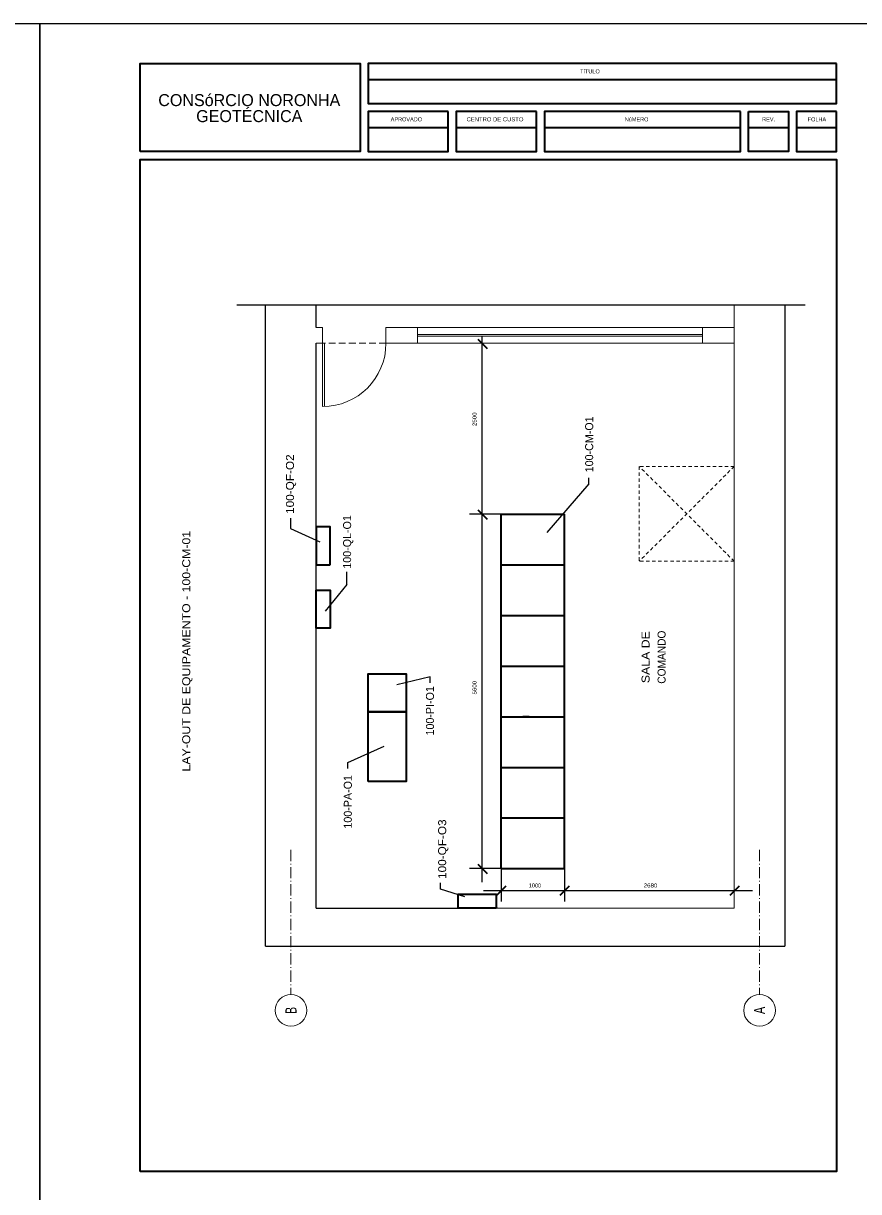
# Model space of a CAD drawing. Extents: x -4160 to -2690, y -474 to 714.
# Drawn here: x -3323.9 to -3115.3, y 422.5 to 714.5 of the extents above; entities that cross this region are included whole.
import ezdxf
from ezdxf.enums import TextEntityAlignment as Align

# ---------------------------------------------------------------- set-up
doc = ezdxf.new("R2010")
doc.units = 0
doc.header["$LTSCALE"] = 0.56
for name, pattern in [('DOT_DASHED', [7.7, 5, -1.2, 0.3, -1.2]), ('MEDIUM_DASHED', [4.5, 3, -1.5]), ('SHORT_DASHED', [2.7, 1.5, -1.2])]:
    doc.linetypes.add(name, pattern=pattern)
for name, color, linetype, lineweight in [('1', 7, 'Continuous', 25), ('2', 7, 'Continuous', 25), ('5', 7, 'Continuous', 35)]:
    doc.layers.add(name, color=color, linetype=linetype, lineweight=lineweight)

msp = doc.modelspace()

# ---------------------------------------------------------------- linework, layer by layer
at = {"layer": '1'}
for p, q in [((-3263.3911, 483.853), (-3263.3911, 644.139)), ((-3250.7364, 638.4791), (-3250.7364, 644.139)), ((-3133.6792, 644.139), (-3133.6792, 483.853)), ((-3250.7364, 493.344), (-3250.7364, 634.5246)), ((-3182.6851, 599.3822), (-3193.141, 587.226)), ((-3182.6851, 599.3822), (-3182.6851, 600.9021)), ((-3243.1054, 574.2496), (-3243.1054, 577.3547)), ((-3243.1054, 574.2496), (-3248.5217, 567.522)), ((-3188.7672, 565.6996), (-3188.7672, 554.6265)), ((-3197.5862, 541.1952), (-3199.1679, 541.1952)), ((-3197.5862, 541.1952), (-3189.3606, 541.1952)), ((-3188.7672, 541.9861), (-3188.7672, 527.7494)), ((-3242.8779, 529.7514), (-3233.7909, 533.8527)), ((-3242.8779, 528.2312), (-3242.8779, 529.7514)), ((-3219.7416, 498.1056), (-3219.7416, 499.6254)), ((-3213.6246, 496.1346), (-3219.7416, 498.1056)), ((-3250.7364, 493.344), (-3215.3027, 493.344)), ((-3205.5111, 493.344), (-3205.8117, 493.344)), ((-3263.3911, 483.853), (-3133.6792, 483.853))]:
    msp.add_line(p, q, dxfattribs=at)
at = {"layer": '1', "lineweight": 13}
for p, q in [((-3146.3342, 644.139), (-3146.3342, 493.344)), ((-3249.1546, 638.4791), (-3250.7364, 638.4791)), ((-3249.1546, 634.5246), (-3249.1546, 638.4791)), ((-3233.336, 638.4791), (-3225.4269, 638.4791)), ((-3233.336, 634.5246), (-3233.336, 638.4791)), ((-3225.4269, 638.4791), (-3154.2433, 638.4791)), ((-3154.2433, 636.739), (-3225.4269, 636.739)), ((-3164.5552, 638.4791), (-3158.7042, 638.4791)), ((-3154.2433, 638.4791), (-3146.3342, 638.4791)), ((-3154.2433, 634.5246), (-3154.2433, 638.4791)), ((-3249.1546, 634.5246), (-3250.7364, 634.5246)), ((-3249.1546, 634.5246), (-3249.1546, 618.706)), ((-3248.68, 634.5246), (-3249.1546, 634.5246)), ((-3248.68, 618.706), (-3248.68, 634.5246)), ((-3154.2433, 636.2645), (-3225.4269, 636.2645)), ((-3225.4269, 634.5246), (-3154.2433, 634.5246)), ((-3165.6768, 634.5246), (-3165.2024, 634.5246)), ((-3165.2024, 634.5246), (-3163.6204, 634.5246)), ((-3154.2433, 634.5246), (-3146.3342, 634.5246)), ((-3250.7364, 493.344), (-3146.3342, 493.344))]:
    msp.add_line(p, q, dxfattribs=at)
at = {"layer": '1', "linetype": 'MEDIUM_DASHED', "lineweight": 13}
msp.add_line((-3233.336, 634.5246), (-3248.68, 634.5246), dxfattribs=at)
at = {"layer": '1', "linetype": 'SHORT_DASHED', "lineweight": 13}
for p, q in [((-3146.3342, 603.7575), (-3170.0617, 580.0296)), ((-3146.3342, 580.0296), (-3170.0617, 603.7575)), ((-3146.3342, 603.7575), (-3170.0617, 603.7575)), ((-3170.0617, 603.7575), (-3170.0617, 580.0296)), ((-3146.3342, 580.0296), (-3170.0617, 580.0296))]:
    msp.add_line(p, q, dxfattribs=at)
at = {"layer": '1', "lineweight": 35}
for p, q in [((-3204.5794, 503.2164), (-3204.5794, 591.8002)), ((-3204.5794, 591.8002), (-3188.7609, 591.8002)), ((-3188.7609, 503.2164), (-3188.7609, 591.8002)), ((-3204.5794, 579.1454), (-3188.7609, 579.1454)), ((-3204.5794, 566.4907), (-3188.7609, 566.4907)), ((-3204.5794, 553.8356), (-3188.7609, 553.8356)), ((-3204.5794, 541.181), (-3188.7609, 541.181)), ((-3204.5794, 528.5261), (-3188.7609, 528.5261)), ((-3204.5794, 515.8713), (-3188.7609, 515.8713)), ((-3204.5794, 503.2164), (-3188.7609, 503.2164))]:
    msp.add_line(p, q, dxfattribs=at)
at = {"layer": '1', "linetype": 'DOT_DASHED', "lineweight": 13}
for p, q in [((-3257.064, 507.9161), (-3257.064, 471.7343)), ((-3140.0067, 507.9161), (-3140.0067, 471.7343))]:
    msp.add_line(p, q, dxfattribs=at)
at = {"layer": '1', "lineweight": 13}
msp.add_lwpolyline([(-3233.336, 634.5246), (-3225.4269, 634.5246), (-3225.4269, 638.4791)], dxfattribs=at)
at = {"layer": '1'}
for points in [[(-3257.2015, 590.8481), (-3257.2015, 588.252), (-3249.855, 584.9225)], [(-3222.2946, 549.6233), (-3222.2946, 551.1436), (-3230.5835, 549.1583)]]:
    msp.add_lwpolyline(points, dxfattribs=at)
msp.add_lwpolyline([(-3188.7609, 591.8002), (-3188.7609, 503.2164), (-3204.5794, 503.2164), (-3204.5794, 591.8002)], close=True, dxfattribs=at)
at = {"layer": '1', "lineweight": 35}
for points in [[(-3250.7364, 563.3412), (-3250.7364, 572.8322), (-3247.2563, 572.8322), (-3247.2563, 563.3412)], [(-3237.7651, 542.3816), (-3237.7651, 551.8727), (-3228.2739, 551.8727), (-3228.2739, 542.3816)], [(-3237.7651, 524.9812), (-3237.7651, 542.3816), (-3228.2739, 542.3816), (-3228.2739, 524.9812)], [(-3205.8117, 493.344), (-3215.3027, 493.344), (-3215.3027, 496.8243), (-3205.8117, 496.8243)]]:
    msp.add_lwpolyline(points, close=True, dxfattribs=at)
at = {"layer": '1', "lineweight": 13}
for centre in [(-3257.0639, 467.7797), (-3140.0064, 467.7797)]:
    msp.add_circle(centre, 3.9546, dxfattribs=at)
msp.add_arc((-3249.1546, 634.5237), 15.8185, 270, 0, dxfattribs=at)
at = {"layer": '5'}
for p, q in [((-3237.7642, 700.48), (-3120.7642, 700.48)), ((-3237.7642, 688.48), (-3217.7642, 688.48)), ((-3215.7642, 688.48), (-3195.7642, 688.48)), ((-3193.7642, 688.48), (-3144.7642, 688.48)), ((-3142.7642, 688.48), (-3132.7642, 688.48)), ((-3130.7642, 688.48), (-3120.7642, 688.48)), ((-3210.4165, 635.5854), (-3208.0764, 633.2435)), ((-3210.4165, 592.8951), (-3208.0764, 590.5532)), ((-3210.4165, 504.3179), (-3208.0764, 501.976)), ((-3205.6449, 496.5703), (-3203.303, 498.9104)), ((-3189.7922, 496.5703), (-3187.4503, 498.9104)), ((-3147.3809, 496.5703), (-3145.039, 498.9104))]:
    msp.add_line(p, q, dxfattribs=at)
at = {"layer": '5', "lineweight": 25}
for p, q in [((-3270.5536, 644.139), (-3128.6508, 644.139)), ((-3209.3255, 499.8557), (-3209.3255, 636.2036)), ((-3204.5794, 591.8002), (-3212.4891, 591.8002)), ((-3204.5794, 503.2164), (-3212.4891, 503.2164)), ((-3204.5794, 503.2164), (-3204.5794, 495.0005)), ((-3188.7609, 503.2164), (-3188.7609, 495.0005)), ((-3141.7753, 497.6574), (-3208.995, 497.6574))]:
    msp.add_line(p, q, dxfattribs=at)
msp.add_lwpolyline([(-3319.7642, 417.48), (-3529.7642, 417.48), (-3529.7642, 714.48), (-3319.7642, 714.48)], close=True, dxfattribs=at)
msp.add_lwpolyline([(-3109.7642, 417.48), (-3319.7642, 417.48), (-3319.7642, 714.48), (-3109.7642, 714.48)], dxfattribs=at)
at = {"layer": '5'}
for points in [[(-3294.7642, 682.48), (-3294.7642, 704.48), (-3239.7642, 704.48), (-3239.7642, 682.48)], [(-3120.7642, 704.48), (-3237.7642, 704.48), (-3237.7642, 694.48), (-3120.7642, 694.48)], [(-3217.7642, 692.48), (-3237.7642, 692.48), (-3237.7642, 682.48), (-3217.7642, 682.48)], [(-3195.7642, 692.48), (-3215.7642, 692.48), (-3215.7642, 682.48), (-3195.7642, 682.48)], [(-3144.7642, 692.48), (-3193.7642, 692.48), (-3193.7642, 682.48), (-3144.7642, 682.48)], [(-3142.7642, 692.48), (-3132.7642, 692.48), (-3132.7642, 682.48), (-3142.7642, 682.48)], [(-3120.7642, 692.48), (-3130.7642, 692.48), (-3130.7642, 682.48), (-3120.7642, 682.48)], [(-3294.7642, 427.48), (-3294.7642, 680.48), (-3120.7642, 680.48), (-3120.7642, 427.48)], [(-3247.2563, 579.1596), (-3247.2563, 588.6508), (-3250.7364, 588.6508), (-3250.7364, 579.1596)]]:
    msp.add_lwpolyline(points, close=True, dxfattribs=at)

# ---------------------------------------------------------------- texts
at = {"layer": '1'}
for s, p in [('100-CM-O1', (-3181.5723, 609.2588)), ('100-QL-O1', (-3242.0396, 584.8681)), ('100-PI-O1', (-3221.3473, 542.6567)), ('100-PA-O1', (-3241.8675, 519.9125))]:
    msp.add_text(s, height=2, rotation=90, dxfattribs=at).set_placement(p, align=Align.CENTER)
for s, height, width, p in [('100-QF-O2', 2, 1.1, (-3256.3136, 599.312)), ('SALA DE', 2, 1.15, (-3167.4862, 556.0666)), ('COMANDO', 2, 0.95, (-3163.4863, 556.0665)), ('100-QF-O3', 2, 1.1, (-3218.2924, 508.0748)), ('B', 2.768, 0.7, (-3255.6798, 467.78)), ('A', 2.768, 0.75, (-3138.6226, 467.78))]:
    msp.add_text(s, height=height, rotation=90, dxfattribs=dict(at, width=width)).set_placement(p, align=Align.CENTER)
at = {"layer": '2', "width": 1.15}
msp.add_text('LAY-OUT DE EQUIPAMENTO - 100-CM-01', height=2, rotation=90, dxfattribs=at).set_placement((-3282.2231, 557.5583), align=Align.CENTER)
at = {"layer": '5'}
for s, height, p in [('TíTULO', 1, (-3182.3847, 701.991)), ('CONSóRCIO NORONHA', 3, (-3267.4749, 693.7961)), ('GEOTÉCNICA', 3, (-3267.475, 689.7961)), ('APROVADO', 1, (-3228.2387, 689.9973)), ('REV.', 1, (-3137.7443, 689.9923)), ('FOLHA', 1, (-3125.6809, 689.9923))]:
    msp.add_text(s, height=height, dxfattribs=at).set_placement(p, align=Align.CENTER)
for s, width, p in [('CENTRO DE CUSTO', 1.1, (-3206.0934, 689.9973)), ('NúMERO', 0.95, (-3170.7228, 689.9923))]:
    msp.add_text(s, height=1, dxfattribs=dict(at, width=width)).set_placement(p, align=Align.CENTER)
at = {"layer": '5', "width": 1.15}
for s, p in [('2500', (-3210.717, 613.8235)), ('5600', (-3210.717, 546.7316))]:
    msp.add_text(s, height=1, rotation=90, dxfattribs=at).set_placement(p)
at = {"layer": '5'}
msp.add_text('1000', height=1, dxfattribs=at).set_placement((-3197.6717, 498.5031))
at = {"layer": '5', "width": 1.15}
msp.add_text('2680', height=1, dxfattribs=at).set_placement((-3168.9514, 498.5031))

doc.saveas('drawing.dxf')
